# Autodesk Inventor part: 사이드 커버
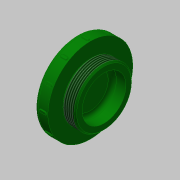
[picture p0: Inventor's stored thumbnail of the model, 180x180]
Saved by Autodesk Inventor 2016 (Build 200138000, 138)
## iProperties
Created: 2016-08
Part Number: 사이드 커버
Material: 스테인리스강
Document SubType Name: Modeling
Designer: mduedu
Density: 8.08 g/cm^3
Appearance: 진녹색
Author: mduedu
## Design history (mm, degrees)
sketch "스케치1"
  geometry: L1 (-5, 0)-(5, 0); L2 (-5, 0)-(-5, 31); L3 (-5, 31)-(5, 31); L4 (5, 31)-(5, 21); L5 (5, 21)-(15, 21); L6 (15, 21)-(15, 16); L7 (15, 16)-(5, 16); L8 (5, 16)-(5, 0); 2 further points
  constraints: 16 end point, 4 parallel, 2 perpendicular, 1 coincident, 1 collinear, 1 horizontal, 1 midpoint, 1 vertical
  dimensions: "d0" = 10 distance of L1.start L1.end; "d2" = 62 diameter of L3 L1; "d3" = 42 diameter of L5 L1; "d4" = 10 distance between parallel lines of L6 L8; "d5" = 5 distance of L5.end L6.end
revolve "회전1" sketch "스케치1" stored, may be unused: angle "d6" = 90 deg
fillet "모깎기1" dims "d7" = 3
sketch "스케치2"
  geometry: L1 (5, -31)-(5, 31) reference; L2 (5, 21)-(15, 21) reference; L3 (0, 0)-(5, 0); L4 (5, 21)-(6, 21); L5 (6, 21)-(6, 20); L6 (6, 20)-(5, 20); L7 (5, 20)-(5, 21)
  constraints: 10 end point, 2 parallel, 1 horizontal, 1 midpoint, 1 perpendicular
  dimensions: "d8" = 1 distance of L2.start L4.end; "d9" = 40 diameter of L6 L3
revolve "회전2" sketch "스케치2" stored, may be unused: angle "d10" = 90 deg
fillet "모깎기2" dims "d11" = 3
feature "스레드1" dims "d12" = 10, "d13" = 0
chamfer "모따기1" distance "d14" = 1; stored, may be unused: second distance "d15" = 2, angle "d16" = 45 deg
node "작업 평면1"
sketch "스케치3"
  geometry: L1 (1, -1)-(-4, -1); L2 (-4, -1)-(-4, 1); L3 (-4, 1)-(1, 1); L4 (1, 1)-(1, -1); 2 further points
  constraints: 8 end point, 2 parallel, 1 horizontal, 1 horizontal alignment, 1 midpoint, 1 perpendicular
  dimensions: "d18" = 2 distance of L3.end L1.start; "d20" = 5 distance of L1.start L1.end; "d21" = 1 distance from line of L4 point (0, 0)
extrude "돌출1" join sketch "스케치3" stored distance "d22" = 10; taper "d23" = 0 deg
fillet "모깎기3" dims "d24" = 1
fillet "모깎기4" dims "d25" = 0.2
sketch "스케치4"
  geometry: 2 further points
  constraints: 1 coincident, 1 other
feature "엠보싱1" sketch "스케치4" dims "d0" = 10, "d2" = 62, "d3" = 42, "d4" = 10, "d5" = 5, "d29" = 0.5, "d30" = 0
node "솔리드1"
pattern_circular "원형 패턴1" dims "d27" = 360 deg
other parameters: "d17" = 31.5
